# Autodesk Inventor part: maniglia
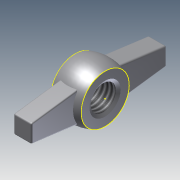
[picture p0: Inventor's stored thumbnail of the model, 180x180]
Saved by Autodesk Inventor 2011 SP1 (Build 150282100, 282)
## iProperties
Created: 2014-01
Part Number: maniglia
Document SubType Name: Modeling
Designer: UTENTE
Density: 1 g/cm^3
Author: UTENTE
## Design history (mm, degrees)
sketch "Schizzo1"
  geometry: L1 (0, 0)-(5, 0); L2 (5, 0)-(5, 8); L3 (-5, 0)-(0, 0); L4 (-5, 0)-(-5, 8); A1 r 13 centre (0, -4) between (5, 8) and (0, 9); A2 r 13 centre (0, -4) between (0, 9) and (-5, 8)
  constraints: 8 end point, 4 point on circle, 2 centre point, 1 collinear, 1 horizontal, 1 perpendicular
revolve "Rivoluzione1" sketch "Schizzo1" stored, may be unused: angle "d4" = 90 deg
sketch "Schizzo2"
  geometry: C1 r 8 at (0, 0) reference; C2 r 8 at (0, 0) reference
  node "Proietta spigoli di taglio1"
sketch "Schizzo3"
  geometry: L1 (-22.5, 0)-(-22.5, -3); L2 (-22.5, -3)-(-4.998, -5.331); L3 (0, 0)-(0, -5.755); L4 (-22.5, 3)-(-4.998, 5.331); L5 (-22.5, 0)-(-22.5, 3); L6 (22.5, -3)-(4.998, -5.331); L7 (22.5, 0)-(22.5, -3); L8 (22.5, 0)-(22.5, 3); L9 (22.5, 3)-(4.998, 5.331); C1 r 9 at (0, 0) reference; A1 r 7.307 centre (0, 0) between (4.998, -5.331) and (4.998, 5.331); A2 r 7.307 centre (0, 0) between (-4.998, 5.331) and (-4.998, -5.331); 1 further point
  constraints: 18 end point, 4 point on circle, 2 centre point, 1 coincident
extrude "Estrusione1" join sketch "Schizzo3" stored distance "d8" = 6; taper "d9" = 0 deg
fillet "Raccordo1" dims "d10" = 0.5
sketch "Schizzo4"
  geometry: C1 r 8 at (0, 0) reference
hole "Hole1" diameter "d13" = 8.376; stored, may be unused: countersink angle "d17" = 90 deg, drill point angle "d19" = 118 deg; dims "d11" = 10, "d12" = 10, "d14" = 6, "d15" = 4, "d16" = 2, "d18" = 8
chamfer "Smusso1" distance "d20" = 1; stored, may be unused: second distance "d21" = 2, angle "d22" = 30 deg
chamfer "Smusso2" distance "d23" = 1; stored, may be unused: second distance "d24" = 2, angle "d25" = 30 deg
node "Solido1"
node "Proietta spigoli di taglio2"
